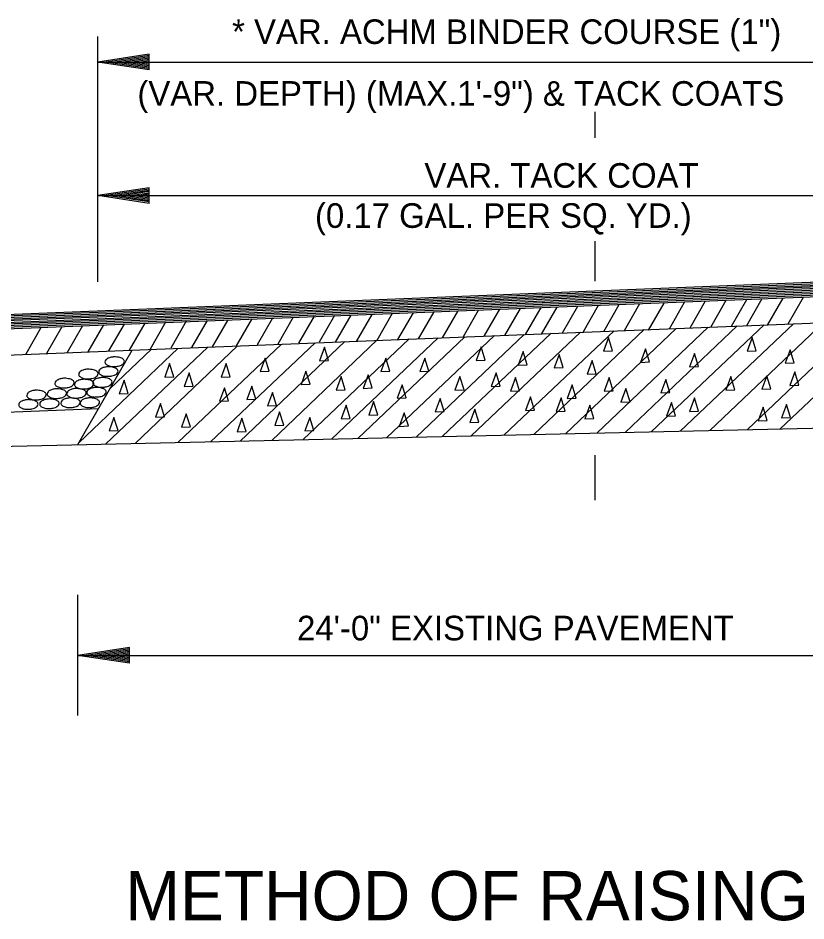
# Model space of a CAD drawing. Extents: x 1955771 to 1955918, y 566326 to 566544.
# Drawn here: x 1955817.46 to 1955836.67, y 566457.51 to 566479.53 of the extents above; entities that cross this region are included whole.
import ezdxf

# ---------------------------------------------------------------- set-up
doc = ezdxf.new("R2010")
doc.units = 0
doc.layers.add('R_Logo', color=7, linetype='Continuous')

msp = doc.modelspace()

# ---------------------------------------------------------------- linework, layer by layer
at = {"layer": 'R_Logo'}
for p, q in [((1955819.4, 566473.095), (1955819.4, 566479.079)), ((1955820.656, 566478.65), (1955819.4, 566478.459)), ((1955820.656, 566478.616), (1955819.609, 566478.459)), ((1955820.656, 566478.271), (1955820.656, 566478.65)), ((1955819.4, 566478.459), (1955843.584, 566478.459)), ((1955820.656, 566478.271), (1955819.4, 566478.459)), ((1955820.656, 566478.302), (1955819.609, 566478.459)), ((1955820.656, 566478.589), (1955819.825, 566478.459)), ((1955820.656, 566478.332), (1955819.825, 566478.459)), ((1955820.656, 566478.553), (1955820.035, 566478.459)), ((1955820.656, 566478.366), (1955820.035, 566478.459)), ((1955820.656, 566478.523), (1955820.248, 566478.459)), ((1955820.656, 566478.396), (1955820.248, 566478.459)), ((1955820.656, 566478.489), (1955820.459, 566478.459)), ((1955820.656, 566478.431), (1955820.459, 566478.459)), ((1955831.531, 566476.612), (1955831.531, 566477.243)), ((1955820.656, 566475.388), (1955819.4, 566475.201)), ((1955820.656, 566475.359), (1955819.609, 566475.201)), ((1955820.656, 566475.326), (1955819.825, 566475.201)), ((1955820.656, 566475.011), (1955820.656, 566475.388)), ((1955819.4, 566475.201), (1955843.584, 566475.201)), ((1955820.656, 566475.011), (1955819.4, 566475.201)), ((1955820.656, 566475.045), (1955819.609, 566475.201)), ((1955820.656, 566475.075), (1955819.825, 566475.201)), ((1955820.656, 566475.297), (1955820.035, 566475.201)), ((1955820.656, 566475.108), (1955820.035, 566475.201)), ((1955820.656, 566475.26), (1955820.248, 566475.201)), ((1955820.656, 566475.139), (1955820.248, 566475.201)), ((1955820.656, 566475.232), (1955820.459, 566475.201)), ((1955820.656, 566475.172), (1955820.459, 566475.201)), ((1955799.162, 566471.432), (1955863.887, 566474.014)), ((1955799.246, 566471.475), (1955863.815, 566474.05)), ((1955799.33, 566471.515), (1955863.744, 566474.086)), ((1955799.415, 566471.56), (1955863.668, 566474.123)), ((1955799.49, 566471.595), (1955863.6, 566474.157)), ((1955831.531, 566473.113), (1955831.531, 566474.085)), ((1955809.045, 566471.784), (1955853.99, 566473.578)), ((1955808.942, 566471.627), (1955854.096, 566473.423)), ((1955808.969, 566471.664), (1955854.07, 566473.462)), ((1955808.994, 566471.705), (1955854.044, 566473.5)), ((1955809.018, 566471.744), (1955854.019, 566473.536)), ((1955808.529, 566470.967), (1955854.524, 566472.797)), ((1955835.595, 566472.678), (1955835.216, 566472.019)), ((1955836.103, 566472.699), (1955835.722, 566472.039)), ((1955836.604, 566472.715), (1955836.229, 566472.063)), ((1955829.697, 566472.448), (1955829.319, 566471.789)), ((1955830.202, 566472.468), (1955829.824, 566471.81)), ((1955830.592, 566472.476), (1955830.215, 566471.819)), ((1955831.099, 566472.494), (1955830.721, 566471.84)), ((1955831.603, 566472.515), (1955831.226, 566471.857)), ((1955832.108, 566472.538), (1955831.732, 566471.878)), ((1955832.614, 566472.557), (1955832.238, 566471.901)), ((1955833.2, 566472.578), (1955832.82, 566471.921)), ((1955833.702, 566472.589), (1955833.331, 566471.942)), ((1955834.211, 566472.621), (1955833.836, 566471.962)), ((1955834.718, 566472.639), (1955834.34, 566471.986)), ((1955835.223, 566472.659), (1955834.845, 566472.003)), ((1955824.167, 566472.235), (1955823.791, 566471.578)), ((1955824.674, 566472.256), (1955824.297, 566471.599)), ((1955825.177, 566472.278), (1955824.8, 566471.622)), ((1955825.571, 566472.283), (1955825.193, 566471.628)), ((1955826.081, 566472.303), (1955825.701, 566471.644)), ((1955826.583, 566472.322), (1955826.205, 566471.666)), ((1955827.089, 566472.344), (1955826.711, 566471.687)), ((1955827.593, 566472.364), (1955827.216, 566471.707)), ((1955828.177, 566472.387), (1955827.799, 566471.728)), ((1955828.679, 566472.398), (1955828.307, 566471.751)), ((1955829.193, 566472.427), (1955828.813, 566471.773)), ((1955819.031, 566472.024), (1955818.655, 566471.369)), ((1955819.539, 566472.046), (1955819.161, 566471.391)), ((1955820.044, 566472.067), (1955819.666, 566471.412)), ((1955820.549, 566472.09), (1955820.17, 566471.433)), ((1955821.056, 566472.11), (1955820.679, 566471.454)), ((1955821.559, 566472.135), (1955821.183, 566471.476)), ((1955822.065, 566472.152), (1955821.689, 566471.495)), ((1955822.569, 566472.172), (1955822.192, 566471.514)), ((1955823.155, 566472.197), (1955822.778, 566471.539)), ((1955823.659, 566472.207), (1955823.286, 566471.56)), ((1955832.262, 566469.424), (1955834.992, 566472.019)), ((1955832.897, 566469.436), (1955835.65, 566472.046)), ((1955833.604, 566469.453), (1955836.367, 566472.075)), ((1955834.323, 566469.47), (1955837.093, 566472.103)), ((1955835.24, 566469.492), (1955838.03, 566472.144)), ((1955836.038, 566469.509), (1955838.851, 566472.173)), ((1955818.021, 566471.987), (1955817.643, 566471.328)), ((1955818.522, 566471.996), (1955818.15, 566471.349)), ((1955826.445, 566469.292), (1955829.071, 566471.784)), ((1955827.165, 566469.309), (1955829.796, 566471.814)), ((1955827.796, 566469.323), (1955830.453, 566471.841)), ((1955828.508, 566469.338), (1955831.175, 566471.865)), ((1955829.305, 566469.356), (1955831.995, 566471.902)), ((1955830.03, 566469.372), (1955832.726, 566471.931)), ((1955830.808, 566469.391), (1955833.502, 566471.96)), ((1955831.573, 566469.407), (1955834.288, 566471.994)), ((1955821.35, 566469.179), (1955823.878, 566471.576)), ((1955822.148, 566469.195), (1955824.699, 566471.611)), ((1955822.869, 566469.211), (1955825.429, 566471.637)), ((1955823.648, 566469.228), (1955826.209, 566471.67)), ((1955824.412, 566469.248), (1955826.99, 566471.704)), ((1955825.101, 566469.262), (1955827.697, 566471.728)), ((1955825.74, 566469.275), (1955828.355, 566471.757)), ((1955818.913, 566469.124), (1955820.243, 566471.433)), ((1955818.94, 566469.17), (1955821.363, 566471.479)), ((1955819.586, 566469.135), (1955822.083, 566471.504)), ((1955819.703, 566470.495), (1955820.707, 566471.45)), ((1955820.309, 566469.153), (1955822.81, 566471.534)), ((1955794.305, 566469.004), (1955819.421, 566470.005)), ((1955813.869, 566469.01), (1955849.109, 566469.803)), ((1955831.531, 566467.769), (1955831.531, 566468.867)), ((1955818.913, 566462.517), (1955818.913, 566465.46)), ((1955820.171, 566464.172), (1955818.913, 566463.983)), ((1955820.171, 566464.142), (1955819.123, 566463.983)), ((1955820.171, 566464.108), (1955819.341, 566463.983)), ((1955820.171, 566464.08), (1955819.548, 566463.983)), ((1955820.171, 566463.795), (1955820.171, 566464.172)), ((1955818.913, 566463.983), (1955844.079, 566463.983)), ((1955820.171, 566463.795), (1955818.913, 566463.983)), ((1955820.171, 566463.828), (1955819.123, 566463.983)), ((1955820.171, 566463.859), (1955819.341, 566463.983)), ((1955820.171, 566463.89), (1955819.548, 566463.983)), ((1955820.171, 566464.044), (1955819.763, 566463.983)), ((1955820.171, 566463.922), (1955819.763, 566463.983)), ((1955820.171, 566464.016), (1955819.973, 566463.983)), ((1955820.171, 566463.955), (1955819.973, 566463.983))]:
    msp.add_line(p, q, dxfattribs=at)
for points in [[(1955831.855, 566471.735), (1955831.734, 566471.404), (1955831.954, 566471.413), (1955831.855, 566471.735)], [(1955835.356, 566471.735), (1955835.235, 566471.403), (1955835.455, 566471.412), (1955835.356, 566471.735)], [(1955824.926, 566471.5), (1955824.805, 566471.168), (1955825.025, 566471.177), (1955824.926, 566471.5)], [(1955828.752, 566471.508), (1955828.631, 566471.177), (1955828.851, 566471.186), (1955828.752, 566471.508)], [(1955829.77, 566471.395), (1955829.649, 566471.064), (1955829.868, 566471.073), (1955829.77, 566471.395)], [(1955832.755, 566471.463), (1955832.634, 566471.132), (1955832.854, 566471.141), (1955832.755, 566471.463)], [(1955833.954, 566471.35), (1955833.833, 566471.019), (1955834.052, 566471.028), (1955833.954, 566471.35)], [(1955836.283, 566471.441), (1955836.162, 566471.109), (1955836.382, 566471.118), (1955836.283, 566471.441)], [(1955823.482, 566471.237), (1955823.362, 566470.905), (1955823.581, 566470.914), (1955823.482, 566471.237)], [(1955826.422, 566471.237), (1955826.302, 566470.905), (1955826.521, 566470.914), (1955826.422, 566471.237)], [(1955827.372, 566471.237), (1955827.252, 566470.905), (1955827.471, 566470.914), (1955827.372, 566471.237)], [(1955830.652, 566471.327), (1955830.531, 566470.996), (1955830.75, 566471.005), (1955830.652, 566471.327)], [(1955831.454, 566471.178), (1955831.333, 566470.846), (1955831.553, 566470.855), (1955831.454, 566471.178)], [(1955821.153, 566471.101), (1955821.032, 566470.77), (1955821.252, 566470.779), (1955821.153, 566471.101)], [(1955822.533, 566471.101), (1955822.412, 566470.77), (1955822.631, 566470.779), (1955822.533, 566471.101)], [(1955824.478, 566470.92), (1955824.357, 566470.589), (1955824.576, 566470.598), (1955824.478, 566470.92)], [(1955820.045, 566470.694), (1955819.924, 566470.363), (1955820.144, 566470.372), (1955820.045, 566470.694)], [(1955821.628, 566470.875), (1955821.507, 566470.544), (1955821.727, 566470.553), (1955821.628, 566470.875)], [(1955825.337, 566470.785), (1955825.216, 566470.453), (1955825.436, 566470.462), (1955825.337, 566470.785)], [(1955825.993, 566470.83), (1955825.872, 566470.498), (1955826.092, 566470.507), (1955825.993, 566470.83)], [(1955828.232, 566470.785), (1955828.111, 566470.453), (1955828.331, 566470.462), (1955828.232, 566470.785)], [(1955829.114, 566470.875), (1955828.993, 566470.544), (1955829.213, 566470.553), (1955829.114, 566470.875)], [(1955829.589, 566470.762), (1955829.468, 566470.431), (1955829.688, 566470.44), (1955829.589, 566470.762)], [(1955831.873, 566470.762), (1955831.752, 566470.431), (1955831.972, 566470.44), (1955831.873, 566470.762)], [(1955833.252, 566470.717), (1955833.132, 566470.385), (1955833.351, 566470.394), (1955833.252, 566470.717)], [(1955834.836, 566470.785), (1955834.715, 566470.453), (1955834.934, 566470.462), (1955834.836, 566470.785)], [(1955835.718, 566470.807), (1955835.597, 566470.476), (1955835.816, 566470.485), (1955835.718, 566470.807)], [(1955836.396, 566470.898), (1955836.275, 566470.566), (1955836.495, 566470.575), (1955836.396, 566470.898)], [(1955822.487, 566470.513), (1955822.366, 566470.182), (1955822.586, 566470.191), (1955822.487, 566470.513)], [(1955823.155, 566470.554), (1955823.035, 566470.223), (1955823.254, 566470.232), (1955823.155, 566470.554)], [(1955826.821, 566470.587), (1955826.7, 566470.256), (1955826.92, 566470.265), (1955826.821, 566470.587)], [(1955830.968, 566470.581), (1955830.847, 566470.25), (1955831.067, 566470.259), (1955830.968, 566470.581)], [(1955832.28, 566470.491), (1955832.159, 566470.159), (1955832.379, 566470.168), (1955832.28, 566470.491)], [(1955823.663, 566470.4), (1955823.543, 566470.069), (1955823.762, 566470.078), (1955823.663, 566470.4)], [(1955827.749, 566470.254), (1955827.628, 566469.922), (1955827.848, 566469.931), (1955827.749, 566470.254)], [(1955829.951, 566470.287), (1955829.83, 566469.956), (1955830.049, 566469.965), (1955829.951, 566470.287)], [(1955830.697, 566470.265), (1955830.576, 566469.933), (1955830.796, 566469.942), (1955830.697, 566470.265)], [(1955833.954, 566470.265), (1955833.833, 566469.933), (1955834.052, 566469.942), (1955833.954, 566470.265)], [(1955820.927, 566470.129), (1955820.806, 566469.797), (1955821.026, 566469.806), (1955820.927, 566470.129)], [(1955825.457, 566470.087), (1955825.336, 566469.756), (1955825.556, 566469.765), (1955825.457, 566470.087)], [(1955826.128, 566470.174), (1955826.008, 566469.843), (1955826.227, 566469.852), (1955826.128, 566470.174)], [(1955831.398, 566470.084), (1955831.277, 566469.752), (1955831.497, 566469.761), (1955831.398, 566470.084)], [(1955833.388, 566470.151), (1955833.267, 566469.82), (1955833.487, 566469.829), (1955833.388, 566470.151)], [(1955835.627, 566470.038), (1955835.506, 566469.707), (1955835.726, 566469.716), (1955835.627, 566470.038)], [(1955836.193, 566470.106), (1955836.072, 566469.775), (1955836.291, 566469.784), (1955836.193, 566470.106)], [(1955821.56, 566469.88), (1955821.439, 566469.549), (1955821.659, 566469.558), (1955821.56, 566469.88)], [(1955823.835, 566469.923), (1955823.715, 566469.591), (1955823.934, 566469.6), (1955823.835, 566469.923)], [(1955826.875, 566469.903), (1955826.754, 566469.571), (1955826.974, 566469.58), (1955826.875, 566469.903)], [(1955828.594, 566469.993), (1955828.473, 566469.662), (1955828.692, 566469.671), (1955828.594, 566469.993)], [(1955819.796, 566469.79), (1955819.675, 566469.458), (1955819.895, 566469.467), (1955819.796, 566469.79)], [(1955822.917, 566469.767), (1955822.796, 566469.435), (1955823.016, 566469.444), (1955822.917, 566469.767)], [(1955824.568, 566469.79), (1955824.447, 566469.458), (1955824.667, 566469.467), (1955824.568, 566469.79)]]:
    msp.add_lwpolyline(points, dxfattribs=at)
for points in [[(1955819.812, 566471.032), (1955819.727, 566471.033), (1955819.636, 566471.066), (1955819.583, 566471.111), (1955819.577, 566471.137), (1955819.599, 566471.193), (1955819.63, 566471.216), (1955819.684, 566471.243), (1955819.765, 566471.262), (1955819.804, 566471.266), (1955819.868, 566471.26), (1955819.937, 566471.249), (1955819.99, 566471.231), (1955820.04, 566471.188), (1955820.049, 566471.16), (1955820.035, 566471.113), (1955819.997, 566471.079), (1955819.959, 566471.055), (1955819.901, 566471.042), (1955819.865, 566471.033), (1955819.812, 566471.032)], [(1955819.17, 566470.732), (1955819.086, 566470.734), (1955818.995, 566470.766), (1955818.941, 566470.812), (1955818.936, 566470.838), (1955818.957, 566470.893), (1955818.989, 566470.917), (1955819.042, 566470.944), (1955819.124, 566470.962), (1955819.163, 566470.966), (1955819.227, 566470.961), (1955819.295, 566470.95), (1955819.349, 566470.931), (1955819.399, 566470.889), (1955819.408, 566470.86), (1955819.393, 566470.813), (1955819.355, 566470.779), (1955819.317, 566470.756), (1955819.26, 566470.742), (1955819.223, 566470.734), (1955819.17, 566470.732)], [(1955819.658, 566470.792), (1955819.573, 566470.794), (1955819.482, 566470.826), (1955819.429, 566470.872), (1955819.423, 566470.897), (1955819.445, 566470.953), (1955819.476, 566470.977), (1955819.53, 566471.003), (1955819.611, 566471.022), (1955819.65, 566471.026), (1955819.714, 566471.02), (1955819.783, 566471.01), (1955819.836, 566470.991), (1955819.886, 566470.948), (1955819.895, 566470.92), (1955819.881, 566470.873), (1955819.843, 566470.839), (1955819.805, 566470.816), (1955819.747, 566470.802), (1955819.711, 566470.794), (1955819.658, 566470.792)], [(1955818.588, 566470.51), (1955818.504, 566470.512), (1955818.413, 566470.544), (1955818.36, 566470.589), (1955818.354, 566470.615), (1955818.376, 566470.671), (1955818.407, 566470.695), (1955818.461, 566470.721), (1955818.542, 566470.74), (1955818.581, 566470.744), (1955818.645, 566470.738), (1955818.714, 566470.728), (1955818.767, 566470.709), (1955818.817, 566470.666), (1955818.826, 566470.638), (1955818.812, 566470.591), (1955818.774, 566470.557), (1955818.736, 566470.534), (1955818.678, 566470.52), (1955818.642, 566470.512), (1955818.588, 566470.51)], [(1955819.067, 566470.484), (1955818.983, 566470.486), (1955818.892, 566470.518), (1955818.839, 566470.564), (1955818.833, 566470.59), (1955818.855, 566470.645), (1955818.886, 566470.669), (1955818.94, 566470.696), (1955819.021, 566470.714), (1955819.06, 566470.718), (1955819.124, 566470.713), (1955819.193, 566470.702), (1955819.246, 566470.683), (1955819.296, 566470.641), (1955819.305, 566470.612), (1955819.291, 566470.565), (1955819.253, 566470.531), (1955819.215, 566470.508), (1955819.157, 566470.494), (1955819.121, 566470.486), (1955819.067, 566470.484)], [(1955819.512, 566470.527), (1955819.428, 566470.529), (1955819.337, 566470.561), (1955819.283, 566470.606), (1955819.278, 566470.632), (1955819.299, 566470.688), (1955819.331, 566470.712), (1955819.384, 566470.738), (1955819.466, 566470.757), (1955819.505, 566470.761), (1955819.569, 566470.755), (1955819.638, 566470.745), (1955819.691, 566470.726), (1955819.741, 566470.683), (1955819.75, 566470.655), (1955819.735, 566470.608), (1955819.697, 566470.574), (1955819.659, 566470.551), (1955819.602, 566470.537), (1955819.566, 566470.529), (1955819.512, 566470.527)], [(1955818.4, 566470.254), (1955818.316, 566470.255), (1955818.225, 566470.287), (1955818.171, 566470.333), (1955818.166, 566470.359), (1955818.188, 566470.414), (1955818.219, 566470.438), (1955818.273, 566470.465), (1955818.354, 566470.483), (1955818.393, 566470.487), (1955818.457, 566470.482), (1955818.526, 566470.471), (1955818.579, 566470.452), (1955818.629, 566470.41), (1955818.638, 566470.381), (1955818.624, 566470.334), (1955818.586, 566470.3), (1955818.548, 566470.277), (1955818.49, 566470.263), (1955818.454, 566470.255), (1955818.4, 566470.254)], [(1955818.879, 566470.262), (1955818.795, 566470.264), (1955818.704, 566470.296), (1955818.65, 566470.341), (1955818.645, 566470.367), (1955818.667, 566470.423), (1955818.698, 566470.446), (1955818.751, 566470.473), (1955818.833, 566470.492), (1955818.872, 566470.496), (1955818.936, 566470.49), (1955819.005, 566470.48), (1955819.058, 566470.461), (1955819.108, 566470.418), (1955819.117, 566470.39), (1955819.103, 566470.343), (1955819.065, 566470.309), (1955819.027, 566470.286), (1955818.969, 566470.272), (1955818.933, 566470.264), (1955818.879, 566470.262)], [(1955819.367, 566470.288), (1955819.283, 566470.289), (1955819.191, 566470.322), (1955819.138, 566470.367), (1955819.132, 566470.393), (1955819.154, 566470.449), (1955819.186, 566470.472), (1955819.239, 566470.499), (1955819.321, 566470.517), (1955819.36, 566470.521), (1955819.423, 566470.516), (1955819.492, 566470.505), (1955819.546, 566470.487), (1955819.596, 566470.444), (1955819.605, 566470.416), (1955819.59, 566470.369), (1955819.552, 566470.335), (1955819.514, 566470.311), (1955819.457, 566470.297), (1955819.42, 566470.289), (1955819.367, 566470.288)], [(1955817.904, 566470.219), (1955817.82, 566470.221), (1955817.729, 566470.253), (1955817.675, 566470.299), (1955817.67, 566470.324), (1955817.692, 566470.38), (1955817.723, 566470.404), (1955817.776, 566470.43), (1955817.858, 566470.449), (1955817.897, 566470.453), (1955817.961, 566470.447), (1955818.03, 566470.437), (1955818.083, 566470.418), (1955818.133, 566470.375), (1955818.142, 566470.347), (1955818.128, 566470.3), (1955818.09, 566470.266), (1955818.051, 566470.243), (1955817.994, 566470.229), (1955817.958, 566470.221), (1955817.904, 566470.219)], [(1955818.221, 566470.005), (1955818.137, 566470.007), (1955818.045, 566470.039), (1955817.992, 566470.085), (1955817.986, 566470.111), (1955818.008, 566470.166), (1955818.04, 566470.19), (1955818.093, 566470.217), (1955818.175, 566470.235), (1955818.213, 566470.239), (1955818.277, 566470.234), (1955818.346, 566470.223), (1955818.399, 566470.204), (1955818.45, 566470.162), (1955818.459, 566470.133), (1955818.444, 566470.086), (1955818.406, 566470.052), (1955818.368, 566470.029), (1955818.311, 566470.015), (1955818.274, 566470.007), (1955818.221, 566470.005)], [(1955818.734, 566470.031), (1955818.65, 566470.033), (1955818.558, 566470.065), (1955818.505, 566470.11), (1955818.499, 566470.136), (1955818.521, 566470.192), (1955818.553, 566470.216), (1955818.606, 566470.242), (1955818.688, 566470.261), (1955818.727, 566470.265), (1955818.791, 566470.259), (1955818.859, 566470.249), (1955818.913, 566470.23), (1955818.963, 566470.187), (1955818.972, 566470.159), (1955818.957, 566470.112), (1955818.919, 566470.078), (1955818.881, 566470.055), (1955818.824, 566470.041), (1955818.787, 566470.033), (1955818.734, 566470.031)], [(1955819.204, 566470.031), (1955819.12, 566470.033), (1955819.029, 566470.065), (1955818.975, 566470.11), (1955818.97, 566470.136), (1955818.992, 566470.192), (1955819.023, 566470.216), (1955819.076, 566470.242), (1955819.158, 566470.261), (1955819.197, 566470.265), (1955819.261, 566470.259), (1955819.33, 566470.249), (1955819.383, 566470.23), (1955819.433, 566470.187), (1955819.442, 566470.159), (1955819.428, 566470.112), (1955819.39, 566470.078), (1955819.352, 566470.055), (1955819.294, 566470.041), (1955819.258, 566470.033), (1955819.204, 566470.031)], [(1955817.708, 566469.988), (1955817.623, 566469.99), (1955817.532, 566470.022), (1955817.479, 566470.068), (1955817.473, 566470.094), (1955817.495, 566470.149), (1955817.526, 566470.173), (1955817.58, 566470.199), (1955817.661, 566470.218), (1955817.7, 566470.222), (1955817.764, 566470.216), (1955817.833, 566470.206), (1955817.886, 566470.187), (1955817.936, 566470.144), (1955817.945, 566470.116), (1955817.931, 566470.069), (1955817.893, 566470.035), (1955817.855, 566470.012), (1955817.797, 566469.998), (1955817.761, 566469.99), (1955817.708, 566469.988)]]:
    msp.add_spline(points, degree=3, dxfattribs=at)

# ---------------------------------------------------------------- texts
for s, height, p in [('* VAR. ACHM BINDER COURSE (1")', 0.6, (1955822.676, 566478.899)), ('(VAR. DEPTH) (MAX.1\'-9") & TACK COATS', 0.6, (1955820.367, 566477.392)), ('VAR. TACK COAT', 0.6, (1955827.365, 566475.392)), ('(0.17 GAL. PER SQ. YD.)', 0.6, (1955824.697, 566474.413)), ('24\'-0" EXISTING PAVEMENT', 0.6, (1955824.26, 566464.35)), ('METHOD OF RAISING GRADE', 1.2, (1955820.069, 566457.522))]:
    msp.add_text(s, height=height, dxfattribs=at).set_placement(p)

doc.saveas('drawing.dxf')
